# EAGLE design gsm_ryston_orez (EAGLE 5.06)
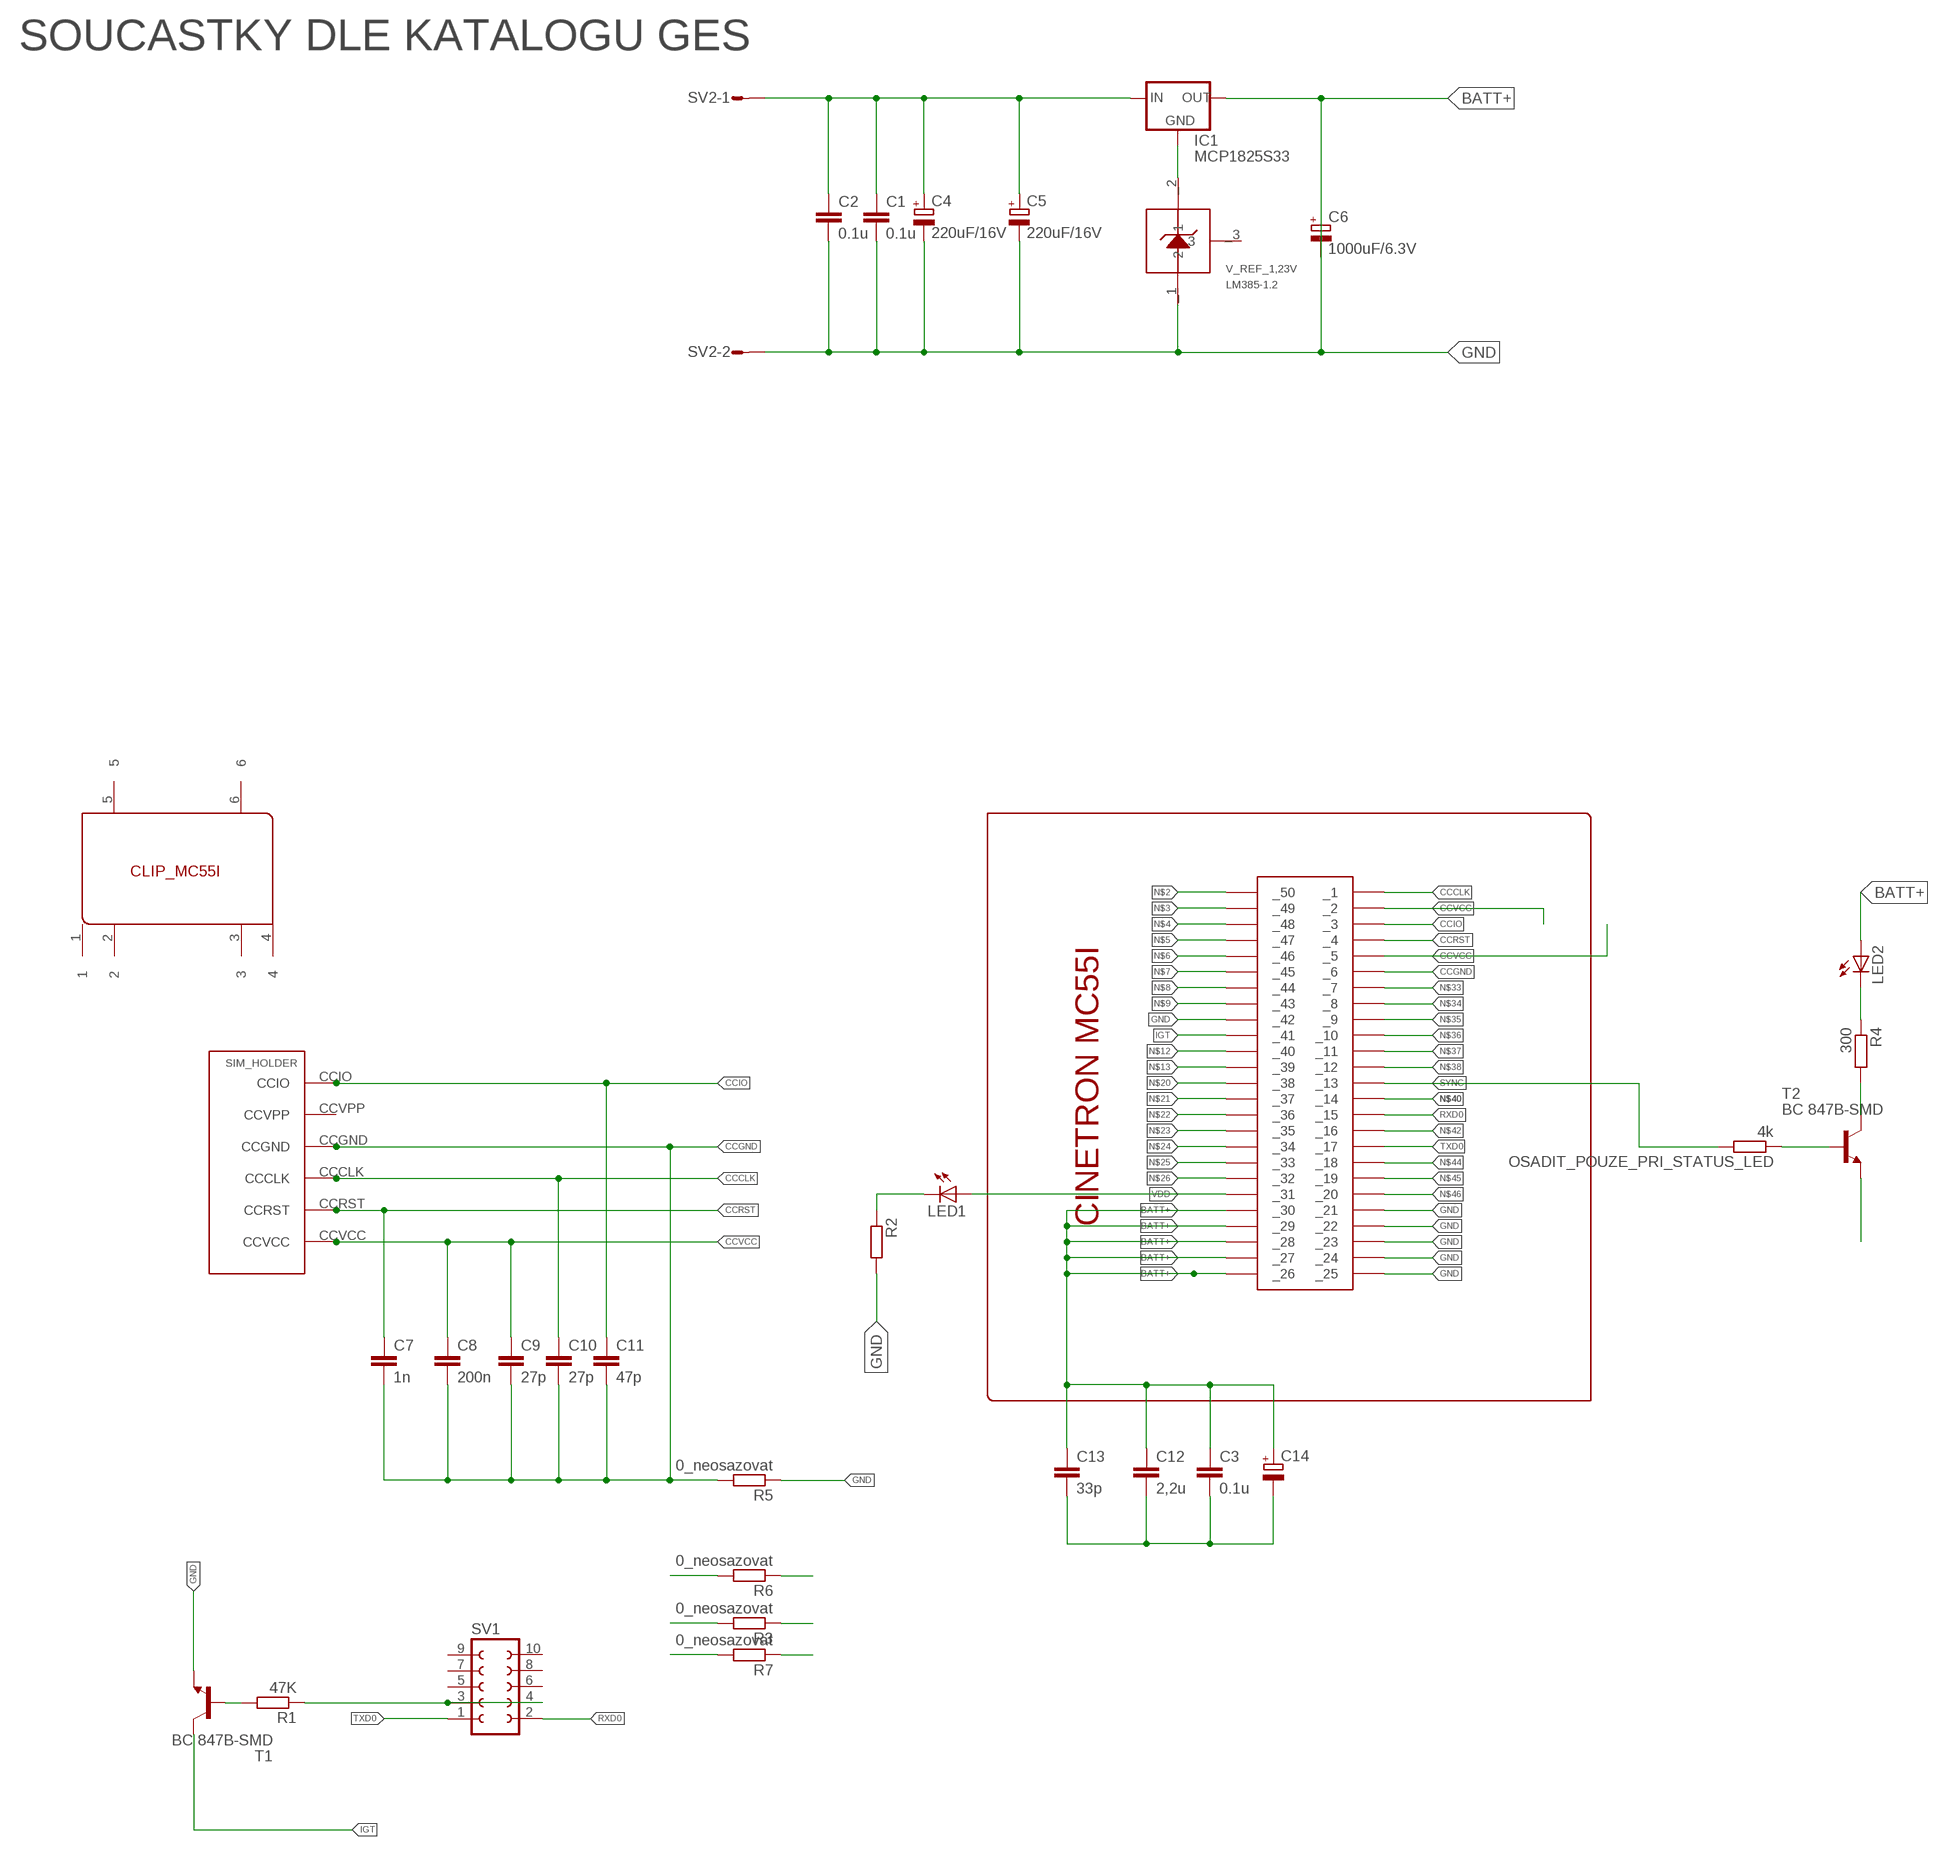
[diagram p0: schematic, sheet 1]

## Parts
C1  0.1u  C-EUC1206K  [C1206K]
C2  0.1u  C-EUC1206K  [C1206K]
C3  0.1u  C-EUC1206K  [C1206K]
C4  220uF/16V  CPOL-EUE2.5-6  [E2,5-6]
C5  220uF/16V  CPOL-EUE2.5-6  [E2,5-6]
C6  1000uF/6.3V  CPOL-EUF  [PANASONIC_F]
C7  1n  C-EUC1206K  [C1206K]
C8  200n  C-EUC1206K  [C1206K]
C9  27p  C-EUC1206K  [C1206K]
C10  27p  C-EUC1206K  [C1206K]
C11  47p  C-EUC1206K  [C1206K]
C12  2,2u  C-EUC1206K  [C1206K]
C13  33p  C-EUC1206K  [C1206K]
C14  CPOL-EUE2.5-6  [E2,5-6]
GND  CLIP_MC55I  [CLIP]
IC1  MCP1825S33  78XXL  [78XXL]
LED1  LEDCHIPLED_1206  [CHIPLED_1206]
LED2  LEDCHIPLED_1206  [CHIPLED_1206]
OSADIT_POUZE_PRI_STATUS_LED  4k  R-EU_M1206  [M1206]
R1  47K  R-EU_M1206  [M1206]
R2  R-EU_M1206  [M1206]
R3  0_neosazovat  R-EU_M1206  [M1206]
R4  300  R-EU_M1206  [M1206]
R5  0_neosazovat  R-EU_M1206  [M1206]
R6  0_neosazovat  R-EU_M1206  [M1206]
R7  0_neosazovat  R-EU_M1206  [M1206]
SIM_HOLDER  SIM_CINETRON_MC55I  [SIM_HOLDER]
SV1  FE05-2W  [FE05-2W]
SV2  L02P  [L02P]
T1  BC 847B-SMD  -NPN-SOT23-EBC  [SOT23-EBC]
T2  BC 847B-SMD  -NPN-SOT23-EBC  [SOT23-EBC]
U$2  CON  [CON]
V_REF_1,23V  LM385-1.2  [TO-92]

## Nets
5VDD: C1.1 C2.1 C4.+ C5.+ IC1.IN SV2.1
BATT+: C3.1 C6.+ C12.1 C13.1 C14.+ IC1.OUT LED2.A U$2.26(_26) U$2.27(_27) U$2.28(_28) U$2.29(_29) U$2.30(_30)
CCCLK: C10.1 SIM_HOLDER.CCCLK U$2.1(_1)
CCGND: C7.2 C8.2 C9.2 C10.2 C11.2 R5.2 SIM_HOLDER.CCGND T2.E U$2.6(_6)
CCIO: C11.1 SIM_HOLDER.CCIO U$2.3(_3)
CCRST: C7.1 SIM_HOLDER.CCRST U$2.4(_4)
CCVCC: C8.1 C9.1 SIM_HOLDER.CCVCC U$2.2(_2) U$2.5(_5)
GND: C1.2 C2.2 C3.2 C4.- C5.- C6.- C12.2 C13.2 C14.- R2.2 R3.1 R3.2 R5.1 R6.1 R6.2 R7.1 R7.2 SV2.2 T1.E U$2.21(_21) U$2.22(_22) U$2.23(_23) U$2.24(_24) U$2.42(_42) U$2._25 V_REF_1,23V._1
IGT: T1.C U$2.41(_41)
N$1: IC1.GND V_REF_1,23V._2
N$2: U$2.50(_50)
N$3: U$2.49(_49)
N$4: U$2.48(_48)
N$5: U$2.47(_47)
N$6: U$2.46(_46)
N$7: U$2.45(_45)
N$8: U$2.44(_44)
N$9: U$2.43(_43)
N$10: LED1.C R2.1
N$11: OSADIT_POUZE_PRI_STATUS_LED.1 T2.B
N$12: U$2.40(_40)
N$13: U$2.39(_39)
N$14: R1.2 T1.B
N$15: R1.1 SV1.3 SV1.4
N$16: R4.2 T2.C
N$17: LED2.C R4.1
N$20: U$2.38(_38)
N$21: U$2.37(_37)
N$22: U$2.36(_36)
N$23: U$2.35(_35)
N$24: U$2.34(_34)
N$25: U$2.33(_33)
N$26: U$2.32(_32)
N$33: U$2.7(_7)
N$34: U$2.8(_8)
N$35: U$2.9(_9)
N$36: U$2.10(_10)
N$37: U$2.11(_11)
N$38: U$2.12(_12)
N$40: U$2.14(_14)
N$42: U$2.16(_16)
N$44: U$2.18(_18)
N$45: U$2.19(_19)
N$46: U$2.20(_20)
RXD0: SV1.2 U$2.15(_15)
SYNC: OSADIT_POUZE_PRI_STATUS_LED.2 U$2.13(_13)
TXD0: SV1.1 U$2.17(_17)
VDD: LED1.A U$2.31(_31)
Unconnected: GND.1 GND.2 GND.3 GND.4 GND.5 GND.6 SV1.5 SV1.6 SV1.7 SV1.8 SV1.9 SV1.10 V_REF_1,23V._3

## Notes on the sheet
- SOUCASTKY DLE KATALOGU GES

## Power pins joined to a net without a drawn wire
CCVPP: SIM_HOLDER.CCVPP

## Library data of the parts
C1-C3 C7-C13 = rcl:C-EU: CAPACITOR, European symbol
C4-C6 C14 = rcl:CPOL-EU: POLARIZED CAPACITOR, European symbol
GND = clip_MC55I:CLIP_MC55I: clip pro MC55I
IC1 = v-reg:78XXL: VOLTAGE REGULATOR
LED1 LED2 = led:LED: LED
OSADIT_POUZE_PRI_STATUS_LED R1-R7 = rcl:R-EU_: RESISTOR, European symbol
SIM_HOLDER = sim_holder:SIM_CINETRON_MC55I: DRZAK SIM KARTY PRO MC55I
SV1 = con-lsta:FE05-2W: FEMALE HEADER
SV2 = con-amp-mt:L02P: AMP MT CONNECTOR
T1 T2 = transistor:*-NPN-: NPN Transistror BF959 corrected 2008.03.06
U$2 = cinetron_MC55I :CON: Konektor pro GSM modul MC55i samicka (na BRD)
V_REF_1,23V = LM385-1.2:LM385-1.2: nampetova reference

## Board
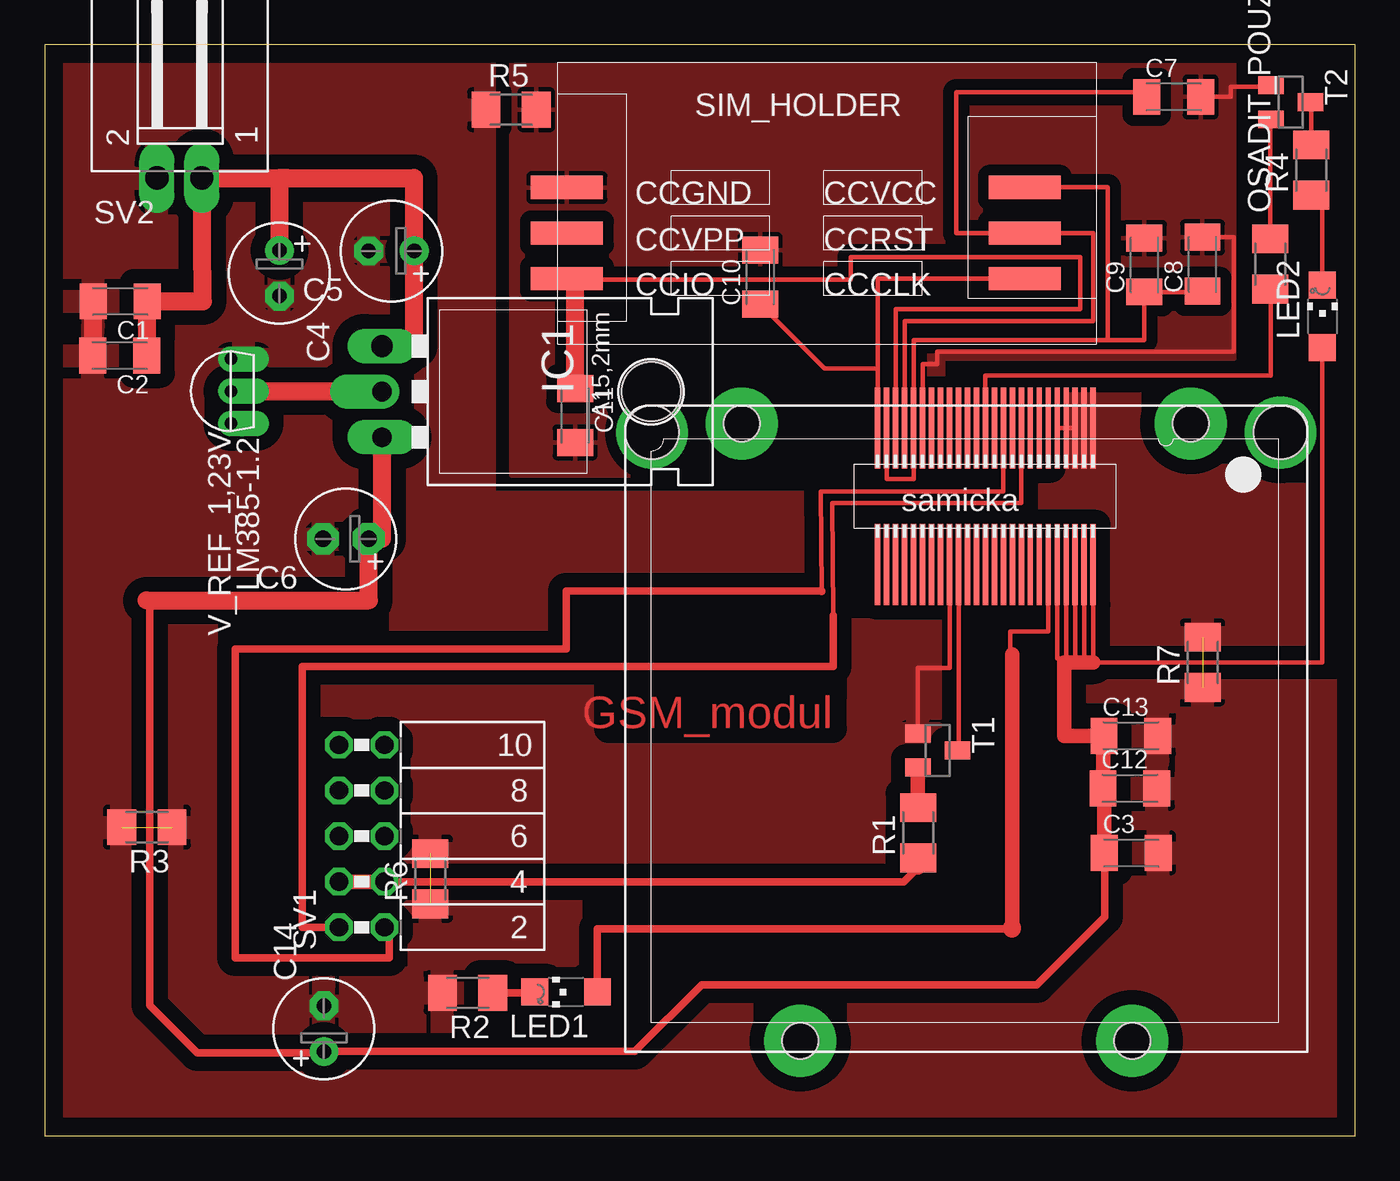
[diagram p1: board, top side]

Size 72.98 x 60.8 mm. Coordinates in mm from the lower left corner, seen from the top.
Outline: 0,0 72.98,0 72.98,60.8 0,60.8 0,0
Copper layers (1*16): Top 0.035mm / dielectric 1.5mm / Bottom 0.035mm
Design rules "default *": minimum track width 10mil, minimum drill 24mil, track to track 5mil, track to pad 5mil, pad to pad 5mil, via to via 5mil, smd to smd 5mil, copper to edge 40mil, drill to drill 8mil, minimum pad ring 10mil, minimum via ring 8mil, stop-mask expansion 4mil, vias tented up to drill 0mil, thermal gap 10mil

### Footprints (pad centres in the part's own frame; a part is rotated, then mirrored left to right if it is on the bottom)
C1206K = smd 1.5 x 2: 1 -1.5,0; 2 1.5,0
E2,5-6 = drill 0.813 pad 1.6 round: + -1.27,0 | drill 0.813 pad 1.6 octagon: - 1.27,0
E2,5-6@1 = drill 0.9 pad 1.778 octagon: + -1.27,0; - 1.27,0
CLIP = drill 2 pad 4 round: 1 0,0; 2 5,-0.5; 3 30,-0.5; 4 35,0; 5 8.25,33.9; 6 26.75,33.9 | hole 2: 8.25,33.9; 26.75,33.9; 5,-0.5; 30,-0.5 | hole 3: 0,0; 35,0
78XXL = drill 1.1 pad 1.93 offset: GND 0,-3.81 | drill 1.2 pad 1.93 long: IN -2.54,-3.81 | drill 1.1 pad 1.93 long: OUT 2.54,-3.81 | hole 3.302: 0,11.176
CHIPLED_1206 = smd 1.5 x 1.5: A 0,-1.75; C 0,1.75
M1206 = smd 1.6 x 2: 1 -1.4,0; 2 1.4,0
SIM_HOLDER = smd 4 x 1.3: CCCLK 26,3.65; CCGND 0.5,8.73; CCIO 0.5,3.65; CCRST 26,6.19; CCVCC 26,8.73; CCVPP 0.5,6.19
FE05-2W = drill 1.016 octagon: 1 -5.08,1.27; 2 -5.08,-1.27; 3 -2.54,1.27; 4 -2.54,-1.27; 5 0,1.27; 6 0,-1.27; 7 2.54,1.27; 8 2.54,-1.27; 9 5.08,1.27; 10 5.08,-1.27
L02P = drill 1.3 long: 1 1.25,-6.25; 2 -1.25,-6.25
SOT23-EBC = smd 1 x 1.4: B 0.95,-1.1; C 0,1.1; E -0.95,-1.1
CON = smd 4.5 x 0.3: 1 3.8,6.05; 2 3.8,5.55; 3 3.8,5.05; 4 3.8,4.55; 5 3.8,4.05; 6 3.8,3.55; 7 3.8,3.05; 8 3.8,2.55; 9 3.8,2.05; 10 3.8,1.55; 11 3.8,1.05; 12 3.8,0.55; 13 3.8,0.05; 14 3.8,-0.45; 15 3.8,-0.95; 16 3.8,-1.45; 17 3.8,-1.95; 18 3.8,-2.45; 19 3.8,-2.95; 20 3.8,-3.45; 21 3.8,-3.95; 22 3.8,-4.45; 23 3.8,-4.95; 24 3.8,-5.45; 26 -3.8,-5.95; 27 -3.8,-5.45; 28 -3.8,-4.95; 29 -3.8,-4.45; 30 -3.8,-3.95; 31 -3.8,-3.45; 32 -3.8,-2.95; 33 -3.8,-2.45; 34 -3.8,-1.95; 35 -3.8,-1.45; 36 -3.8,-0.95; 37 -3.8,-0.45; 38 -3.8,0.05; 39 -3.8,0.55; 40 -3.8,1.05; 41 -3.8,1.55; 42 -3.8,2.05; 43 -3.8,2.55; 44 -3.8,3.55; 45 -3.8,3.05; 46 -3.8,4.05; 47 -3.8,4.55; 48 -3.8,5.05; 49 -3.8,5.55; 50 -3.8,6.05; _25 3.8,-5.95
TO-92 = drill 0.7 pad 1.422 offset: _1 -1.8,0; _2 0,0; _3 1.8,0

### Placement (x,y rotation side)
C1  4.2,46.51 180 top
C2  4.18,43.48 180 top
C3  60.51,15.77 0 top
C4  13.07,48.07 270 top
C5  19.3,49.31 180 top
C6  1000uF/6.3V  [E2,5-6@1]  16.76,33.28 180 top
C7  62.87,57.9 0 top
C8  64.48,48.57 90 top
C9  61.24,48.54 90 top
C10  39.84,47.86 90 top
C11  29.54,40.15 270 top
C12  60.44,19.38 0 top
C13  60.49,22.3 0 top
C14  15.54,5.98 90 top
GND  68.82,39.2 180 top
IC1  22.59,41.48 270 top
LED1  29.03,8.03 90 top
LED2  71.16,45.67 0 top
OSADIT_POUZE_PRI_STATUS_LED  68.26,48.59 270 top
R1  48.64,16.89 90 top
R2  23.54,7.98 180 top
R3  5.69,17.21 180 top
R4  70.53,53.82 90 top
R5  25.97,57.19 0 top
R6  21.47,14.34 90 top
R7  64.49,26.39 90 top
SIM_HOLDER  28.58,44.12 0 top
SV1  17.65,16.71 90 top
SV2  7.49,59.63 0 top
T1  49.73,21.48 270 top
T2  69.39,57.59 270 top
U$2  52.44,35.65 90 top
V_REF_1,23V  10.36,41.5 270 top

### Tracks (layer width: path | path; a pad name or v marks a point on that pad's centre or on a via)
5VDD
  Top 1.016: C4.+ 13.07,53.38 13.5,53.38 | 13.5,53.38 20.56,53.38 20.56,49.31 | 20.56,49.31 C5.+ | 20.56,49.31 20.56,44.02 IC1.IN | C2.1 5.7,43.48 C1.1 8.8,46.51 SV2.1 8.8,53.38 13.5,53.38
BATT+
  Top 0.254: U$2.26 58.39,26.39 71.16,26.39 LED2.A | U$2.27 57.89,26.39 57.72,26.39 | U$2.28 57.39,26.39 57.31,26.39 | 56.89,26.61 56.89,26.39 | 56.89,26.61 U$2.29 | U$2.30 56.39,26.61 56.89,26.61
  Top 0.406: 56.77,22.29 56.77,22.35 | 58.99,15.77 C3.1 59.04,15.75 59.04,12.22 55.26,8.43 36.57,8.43 32.85,4.71 C14.+ 15.48,4.65 8.48,4.65 5.84,7.29 5.84,29.85 5.66,29.85
  Top 0.813: 58.39,26.39 57.72,26.39 57.31,26.39 56.89,26.39 56.77,26.39 56.77,22.29 58.99,22.29 C13.1 58.94,22.3 C12.1 59.01,19.38 C3.1
  Top 1.016: IC1.OUT 18.78,33.28 C6.+ 18.04,33.28 18.04,29.85 5.66,29.85
CCCLK
  Top 0.254: SIM_HOLDER.CCCLK 46.39,47.77 46.39,42.75 | 46.39,42.75 U$2.1 | 46.39,42.75 43.45,42.75 C10.1
CCGND
  Top 0.254: U$2.6 48.89,43.01 49.69,43.01 49.69,43.7 66.23,43.7 66.23,50.07 C8.2 | T2.E 68.29,58.47 66.05,58.47 66.05,57.9 C7.2
  pour Top (isolate 0.61): 25.98,60.8 25.98,36.8 49.98,36.8 50.04,43.32 66.25,43.32 66.25,60.82
CCIO
  Top 0.254: SIM_HOLDER.CCIO 29.08,47.73 29.6,47.73 44.88,47.73 44.88,48.98 57.66,48.98 57.66,46.06 47.39,46.06 U$2.3 47.37,39.45
  Top 1.016: C11.1 29.54,47.73 29.6,47.73
CCRST
  Top 0.254: U$2.4 47.9,39.45 47.9,45.4 58.39,45.4 58.39,50.31 SIM_HOLDER.CCRST 50.77,50.31 50.77,58.15 61.37,58.15 C7.1
CCVCC
  Top 0.254: SIM_HOLDER.CCVCC 59.19,52.86 59.19,44.36 | 59.19,44.36 48.4,44.36 U$2.5 48.38,36.6 46.89,36.6 U$2.2 | C8.1 64.48,47.04 C9.1 61.24,44.36 59.19,44.36
GND  (3 unrouted)
  Top 0.254: U$2.21 U$2.22 | U$2.22 U$2.23 U$2.22 | U$2.42 50.39,26.07 48.61,26.07 48.61,22.43 T1.E
  Top 1.016: C1.2 2.7,43.48 C2.2
  pour Top (isolate 0.813): 72.91,60.79 72.84,0.13 0.84,0.13 0.98,60.8 24.47,61.33 24.47,35.33 52.47,35.33 52.47,42.04 68.2,42.04 68.2,60.79
IGT
  Top 0.254: U$2.41 50.9,31.85 50.9,21.48 T1.C
N$1
  Top 1.016: IC1.GND 18.78,41.5 V_REF_1,23V._2
N$10
  Top 0.406: R2.1 27.28,7.98 LED1.C
N$11
  Top 0.254: OSADIT_POUZE_PRI_STATUS_LED.1 68.26,56.64 T2.B
N$14
  Top 0.813: T1.B R1.2
N$15
  Top 0.406: SV1.4 47.85,14.17 48.64,14.96
  Top 0.813: SV1.3 SV1.4 | 48.64,14.96 R1.1
N$16
  Top 0.254: R4.2 70.53,57.59 T2.C
N$17
  Top 0.254: LED2.C 71.16,52.42 R4.1
RXD0
  Top 0.254: U$2.15 53.39,35.9 43.22,35.9 43.27,30.34
  Top 0.406: SV1.2 19.17,11.63 19.17,9.92 10.59,9.92 10.59,27.13 29.04,27.13 29.04,30.37 43.27,30.37 43.27,30.34
SYNC
  Top 0.254: U$2.13 52.39,42.37 68.29,42.37 68.29,47.19 OSADIT_POUZE_PRI_STATUS_LED.2
TXD0
  Top 0.254: U$2.17 54.39,35.28 43.86,35.28 43.9,28.99 43.9,28.61
  Top 0.406: SV1.1 14.32,11.63 14.32,26.17 43.9,26.17 43.9,28.99
VDD
  Top 0.254: 53.78,26.89 53.78,28.12 55.88,28.12 U$2.31 | 53.78,26.89 53.78,26.82 | 53.87,26.82 53.87,26.89 53.78,26.89
  Top 0.406: LED1.A 30.78,11.54 53.87,11.54
  Top 0.813: 53.87,11.62 53.87,26.82
  Top 1.016: 53.87,11.54 53.87,11.62

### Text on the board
Top: GSM_modul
